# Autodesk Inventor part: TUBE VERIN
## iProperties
Created: 2004-11
Part Number: TUBE VERIN
Document SubType Name: Modeling
Designer: Bruno
Manufacturer: Standard
Standards Organization: Custom
Author: Bruno
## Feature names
1. Base1
2. Extrusion1
